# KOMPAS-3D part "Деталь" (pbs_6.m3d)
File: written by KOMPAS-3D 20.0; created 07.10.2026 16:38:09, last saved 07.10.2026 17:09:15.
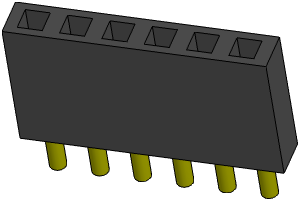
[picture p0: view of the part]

Document properties: Полное имя файла: D:\myProjects\Progect_esp32\box_compas\pbs_6.m3d

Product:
- Part/product: Деталь
    Масса: 0.00190694

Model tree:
1. Эскиз:1
2. Элемент выдавливания:1
     Расстояние 1 = 8.5
3. Эскиз:2  (with: Элемент выдавливания:1)
4. Элемент выдавливания:2
     Расстояние 1 = 3
5. Массив по сетке:2  (with: Элемент выдавливания:2, Эскиз:2)  (6 pattern instances)
     Шаг 1 = 2.54; Угол раствора = 90
6. Эскиз:3  (with: Элемент выдавливания:1)
7. Элемент выдавливания:3
     Расстояние 2 = 8
8. Массив по сетке:3  (with: Элемент выдавливания:3, Эскиз:3)  (6 pattern instances)
     Шаг 1 = 2.54; Угол раствора = 90; Геометрический массив = 128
